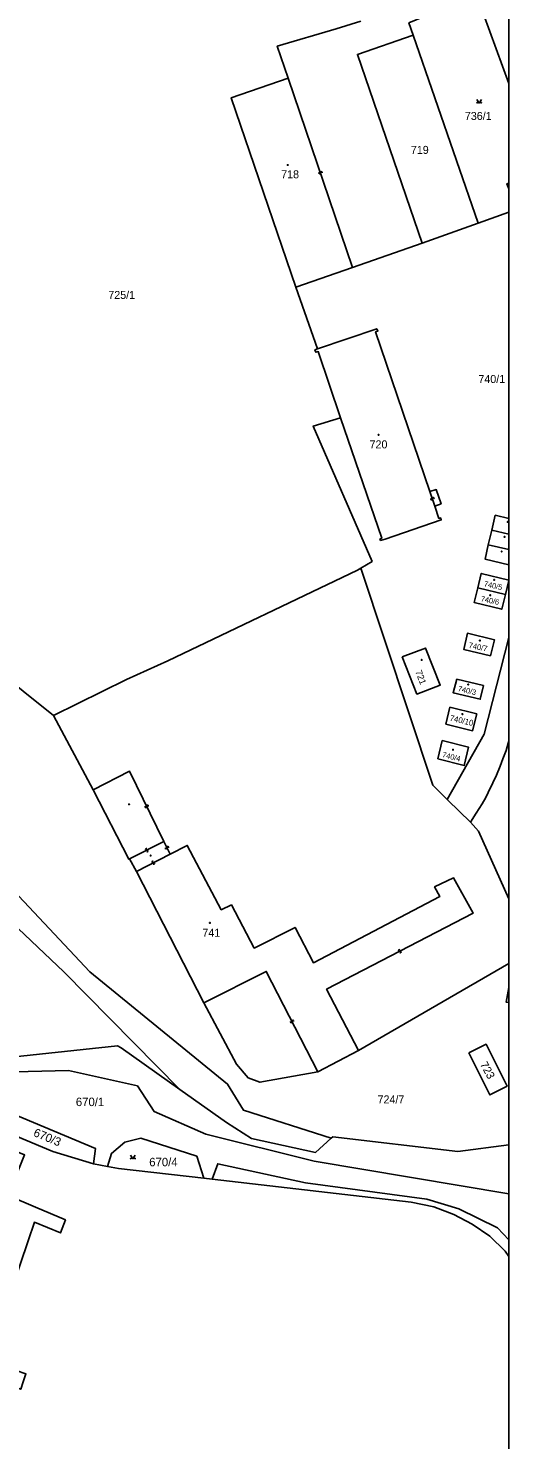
# Model space of a CAD drawing. Extents: x -600391 to -599491, y -1160176 to -1159402.
# Drawn here: x -599592.8 to -599490.8, y -1159973.1 to -1159673.2 of the extents above; entities that cross this region are included whole.
import ezdxf

# ---------------------------------------------------------------- set-up
doc = ezdxf.new("R2010")
doc.units = 0
for name, color, linetype in [('Level 1', 7, 'Continuous'), ('Level 13', 7, 'Continuous'), ('Level 3', 7, 'Continuous'), ('Level 4', 7, 'Continuous'), ('Level 5', 7, 'Continuous'), ('Vrstva 63', 7, 'Continuous')]:
    doc.layers.add(name, color=color, linetype=linetype)

msp = doc.modelspace()

# ---------------------------------------------------------------- linework, layer by layer
at = {"layer": 'Level 1'}
for p, q in [((-599497.62, -1159666.09), (-599490.77, -1159684.95)), ((-599490.77, -1159712.29), (-599497.24, -1159714.63)), ((-599494.38, -1159779.82), (-599490.77, -1159780.67)), ((-599490.77, -1159783.97), (-599495.12, -1159782.97)), ((-599491.49, -1159793.51), (-599490.77, -1159790.54)), ((-599522.69, -1159890.4), (-599490.77, -1159871.89))]:
    msp.add_line(p, q, dxfattribs=at)
for points in [[(-599497.62, -1159666.09), (-599511.98, -1159672.07), (-599511.1, -1159674.67)], [(-599537.6, -1159683.79), (-599539.94, -1159677.03), (-599527.44, -1159673.35), (-599522.15, -1159671.73)], [(-599511.1, -1159674.67), (-599522.91, -1159678.77), (-599509.17, -1159718.89)], [(-599511.1, -1159674.67), (-599497.24, -1159714.63)], [(-599537.6, -1159683.79), (-599549.69, -1159687.96), (-599535.97, -1159728.23)], [(-599490.77, -1159707.33), (-599491.15, -1159706.23), (-599490.77, -1159706.1)], [(-599497.24, -1159714.63), (-599509.17, -1159718.89)], [(-599509.17, -1159718.89), (-599523.93, -1159724.01)], [(-599523.93, -1159724.01), (-599535.97, -1159728.23)], [(-599535.97, -1159728.23), (-599531.41, -1159741.34)], [(-599531.41, -1159741.34), (-599518.8, -1159737.05), (-599518.59, -1159737.57), (-599519.05, -1159737.74), (-599507.52, -1159771.61)], [(-599531.41, -1159741.34), (-599531.92, -1159741.55), (-599531.74, -1159742.03), (-599531.22, -1159741.9), (-599526.51, -1159755.98)], [(-599526.51, -1159755.98), (-599532.3, -1159757.75), (-599519.81, -1159786.48), (-599522.15, -1159787.9)], [(-599506.45, -1159774.72), (-599505.61, -1159777.37), (-599505.23, -1159777.23), (-599505.1, -1159777.68), (-599517.02, -1159781.75), (-599517.99, -1159782.03), (-599518.12, -1159781.73), (-599517.74, -1159781.57), (-599526.51, -1159755.98)], [(-599753.71, -1159763.28), (-599749.4, -1159769.94), (-599727.76, -1159798.93), (-599714.51, -1159816.26), (-599697.25, -1159839.07), (-599689.39, -1159847.67), (-599678.59, -1159857.57), (-599666.21, -1159866.59), (-599654.11, -1159874.19), (-599640.99, -1159880.78), (-599626.25, -1159886.88), (-599606.79, -1159894.4), (-599598.5, -1159895.01), (-599584.26, -1159894.68), (-599569.62, -1159897.92), (-599566.09, -1159903.38), (-599555.13, -1159908.18), (-599532.12, -1159913.92), (-599490.77, -1159920.87)], [(-599507.52, -1159771.61), (-599506.18, -1159771.22), (-599505.14, -1159774.24), (-599506.45, -1159774.72)], [(-599494.38, -1159779.82), (-599493.64, -1159776.69), (-599490.77, -1159777.39)], [(-599495.12, -1159782.97), (-599494.38, -1159779.82)], [(-599495.12, -1159782.97), (-599495.8, -1159786), (-599490.77, -1159787.2)], [(-599522.15, -1159787.9), (-599522.86, -1159788.33), (-599563.15, -1159807.58), (-599571.93, -1159811.59), (-599587.46, -1159819.24)], [(-599503.87, -1159837.09), (-599506.89, -1159834.06), (-599522.15, -1159787.9)], [(-599490.77, -1159790.44), (-599496.6, -1159789.04), (-599497.33, -1159792.11)], [(-599497.33, -1159792.11), (-599498.09, -1159795.25), (-599492.25, -1159796.66), (-599491.49, -1159793.51)], [(-599491.49, -1159793.51), (-599497.33, -1159792.11)], [(-599560.62, -1159898.7), (-599573.09, -1159889.87), (-599573.88, -1159889.45), (-599607.04, -1159892.98), (-599652.03, -1159872.89), (-599667.25, -1159861.02), (-599687.91, -1159844.99), (-599722.17, -1159800.44)], [(-599503.87, -1159837.09), (-599495.98, -1159823.18), (-599490.77, -1159802.63)], [(-599494.62, -1159806.55), (-599493.8, -1159803.13), (-599499.54, -1159801.75), (-599500.34, -1159805.17), (-599494.62, -1159806.55)], [(-599657.03, -1159804.78), (-599613.02, -1159847.44), (-599585.27, -1159873.69), (-599560.62, -1159898.7)], [(-599513.43, -1159806.76), (-599508.42, -1159804.9), (-599505.31, -1159812.75), (-599510.27, -1159814.68), (-599513.43, -1159806.76)], [(-599600.38, -1159808.9), (-599587.46, -1159819.24)], [(-599501.83, -1159811.48), (-599496.14, -1159812.86), (-599496.82, -1159815.76), (-599502.58, -1159814.38), (-599501.83, -1159811.48)], [(-599503.28, -1159817.43), (-599497.58, -1159818.9), (-599498.44, -1159822.46), (-599504.12, -1159821.07), (-599503.28, -1159817.43)], [(-599587.46, -1159819.24), (-599579, -1159835.01)], [(-599504.92, -1159824.53), (-599499.29, -1159825.99), (-599500.23, -1159829.88), (-599505.82, -1159828.43), (-599504.92, -1159824.53)], [(-599490.77, -1159824.68), (-599490.89, -1159825.1), (-599491.35, -1159826.63), (-599492, -1159828.42), (-599492.62, -1159830.02), (-599493.41, -1159831.88), (-599494.15, -1159833.56), (-599495.14, -1159835.61), (-599495.65, -1159836.63), (-599496.44, -1159837.99), (-599497.66, -1159839.95), (-599498.89, -1159841.91)], [(-599528.47, -1159909.07), (-599547.1, -1159903.06), (-599550.47, -1159897.53), (-599579.75, -1159873.69), (-599603.52, -1159848.43), (-599607.94, -1159843.45), (-599616.53, -1159835.36)], [(-599579, -1159835.01), (-599571.47, -1159849.76), (-599571.28, -1159849.7)], [(-599498.89, -1159841.91), (-599503.68, -1159837.21), (-599503.87, -1159837.09)], [(-599498.89, -1159841.91), (-599497.17, -1159843.78), (-599490.77, -1159858.21)], [(-599571.28, -1159849.7), (-599569.83, -1159852.34)], [(-599569.83, -1159852.34), (-599555.51, -1159880.29)], [(-599490.77, -1159880.22), (-599491.31, -1159880.16), (-599490.77, -1159877.02)], [(-599555.51, -1159880.29), (-599548.61, -1159893.33), (-599546.14, -1159896.21), (-599543.62, -1159897.15), (-599531.3, -1159894.91)], [(-599578.95, -1159914.46), (-599578.55, -1159911.22), (-599596.11, -1159903.88), (-599598.49, -1159901.19), (-599626.57, -1159890.89), (-599627.69, -1159893.15)], [(-599531.3, -1159894.91), (-599522.69, -1159890.4)], [(-599499.27, -1159890.9), (-599495.59, -1159889.09), (-599491.11, -1159897.96), (-599494.77, -1159899.84), (-599499.27, -1159890.9)], [(-599528.47, -1159909.07), (-599531.84, -1159912.06), (-599545.39, -1159909.12), (-599550.74, -1159905.69), (-599560.62, -1159898.7)], [(-599599.13, -1159907.08), (-599587.58, -1159911.88), (-599578.95, -1159914.46)], [(-599490.77, -1159910.46), (-599501.58, -1159911.87), (-599528.1, -1159908.74), (-599528.47, -1159909.07)], [(-599624.96, -1159950.28), (-599610.29, -1159954.8), (-599610.87, -1159956.69), (-599596.78, -1159961.57), (-599594.41, -1159962.38), (-599593.86, -1159960.78), (-599593.31, -1159959.08), (-599593.73, -1159958.98), (-599596.14, -1159958.11), (-599601.47, -1159956.19), (-599592.82, -1159930.88), (-599591.51, -1159926.91), (-599585.94, -1159929.16), (-599584.91, -1159926.39), (-599591.27, -1159923.7), (-599597.04, -1159921.2), (-599593.57, -1159912.61), (-599599.02, -1159910.35)], [(-599555.49, -1159917.56), (-599557.01, -1159912.88), (-599568.88, -1159909.04), (-599572.3, -1159909.85), (-599575.12, -1159912.26), (-599575.95, -1159915.03)], [(-599578.95, -1159914.46), (-599575.95, -1159915.03)], [(-599490.77, -1159930.62), (-599493.16, -1159928.08), (-599501.37, -1159924.05), (-599508.17, -1159922.03), (-599533.9, -1159918.51), (-599552.56, -1159914.48), (-599553.78, -1159917.76)], [(-599575.95, -1159915.03), (-599573.62, -1159915.47), (-599555.49, -1159917.56)], [(-599555.49, -1159917.56), (-599553.78, -1159917.76)], [(-599553.78, -1159917.76), (-599511.52, -1159922.64), (-599506.67, -1159923.62), (-599502.42, -1159925.23), (-599498.52, -1159927.32), (-599494.79, -1159929.88), (-599491.53, -1159933.07), (-599490.77, -1159934.15)]]:
    msp.add_lwpolyline(points, dxfattribs=at)
at = {"layer": 'Level 13'}
for centre, start, end in [((-599530.93, -1159703.96), 145.9302, 18.5202), ((-599530.58, -1159703.84), 326.1446, 198.2426), ((-599507.16, -1159773.22), 146.1441, 18.7341), ((-599506.82, -1159773.1), 326.3586, 198.4566), ((-599567.83, -1159838.61), 153.1973, 25.7873), ((-599567.49, -1159838.45), 333.4117, 205.5097), ((-599567.73, -1159847.68), 64.3512, 296.9412), ((-599567.57, -1159848), 244.5657, 116.6637), ((-599563.53, -1159847.4), 153.2989, 25.8889), ((-599563.19, -1159847.24), 333.5134, 205.6114), ((-599566.34, -1159850.35), 64.2982, 296.8882), ((-599566.18, -1159850.67), 244.5126, 116.6106), ((-599513.99, -1159869.16), 64.5572, 297.1472), ((-599513.83, -1159869.48), 244.7717, 116.8697), ((-599536.95, -1159884.33), 154.6216, 26.7196), ((-599536.63, -1159884.17), 334.4072, 206.9972)]:
    msp.add_arc(centre, 0.184, start, end, dxfattribs=at)
at = {"layer": 'Level 3'}
for points in [[(-599537.6, -1159683.79), (-599523.93, -1159724.01)], [(-599507.52, -1159771.61), (-599506.45, -1159774.72)], [(-599579, -1159835.01), (-599571.29, -1159831.09), (-599564.02, -1159845.97)], [(-599564.02, -1159845.97), (-599571.28, -1159849.7)], [(-599562.69, -1159848.68), (-599569.83, -1159852.34)], [(-599564.02, -1159845.97), (-599562.69, -1159848.68)], [(-599562.69, -1159848.68), (-599559.05, -1159846.83), (-599551.82, -1159860.51), (-599549.67, -1159859.48), (-599544.82, -1159868.65), (-599536.14, -1159864.24), (-599532.27, -1159871.75), (-599505.39, -1159857.67), (-599506.53, -1159855.66), (-599502.53, -1159853.71), (-599498.36, -1159861.26), (-599529.46, -1159877.38), (-599522.69, -1159890.4)], [(-599531.3, -1159894.91), (-599542.28, -1159873.59), (-599555.51, -1159880.29)]]:
    msp.add_lwpolyline(points, dxfattribs=at)
at = {"layer": 'Level 5'}
for points in [[(-599497.56, -1159688.34), (-599497.06, -1159689.09), (-599496.56, -1159688.34)], [(-599571.09, -1159912.67), (-599570.59, -1159913.42), (-599570.09, -1159912.67)]]:
    msp.add_lwpolyline(points, dxfattribs=at)
for centre, radius in [((-599497.51, -1159689.04), 0.05), ((-599496.61, -1159689.04), 0.05), ((-599537.7, -1159702.26), 0.09), ((-599537.7, -1159702.26), 0.0521), ((-599518.42, -1159759.6), 0.09), ((-599518.42, -1159759.6), 0.0521), ((-599491, -1159778.1), 0.09), ((-599491, -1159778.1), 0.0521), ((-599491.66, -1159781.29), 0.09), ((-599491.66, -1159781.29), 0.0521), ((-599492.28, -1159784.38), 0.09), ((-599492.28, -1159784.38), 0.0521), ((-599493.87, -1159790.43), 0.09), ((-599493.87, -1159790.43), 0.0521), ((-599494.71, -1159793.68), 0.09), ((-599494.71, -1159793.68), 0.0521), ((-599496.9, -1159803.32), 0.09), ((-599496.9, -1159803.32), 0.0521), ((-599509.26, -1159807.42), 0.09), ((-599509.26, -1159807.42), 0.0521), ((-599499.37, -1159812.64), 0.09), ((-599499.37, -1159812.64), 0.0521), ((-599500.61, -1159818.93), 0.09), ((-599500.61, -1159818.93), 0.0521), ((-599502.61, -1159826.5), 0.09), ((-599502.61, -1159826.5), 0.0521), ((-599571.39, -1159838.1), 0.09), ((-599571.39, -1159838.1), 0.0521), ((-599566.82, -1159848.99), 0.09), ((-599566.82, -1159848.99), 0.0521), ((-599554.23, -1159863.31), 0.09), ((-599554.23, -1159863.31), 0.0521), ((-599571.04, -1159913.37), 0.05), ((-599570.14, -1159913.37), 0.05)]:
    msp.add_circle(centre, radius, dxfattribs=at)
at = {"layer": 'Vrstva 63'}
msp.add_lwpolyline([(-600391.01, -1159401.77), (-599490.77, -1159401.77), (-599490.77, -1160176.08), (-600391.01, -1160176.08)], close=True, dxfattribs=at)

# ---------------------------------------------------------------- texts
at = {"layer": 'Level 4'}
for s, height, p in [('736/1', 1.7, (-599500.09, -1159692.69)), ('719', 1.7, (-599511.56, -1159699.9)), ('718', 1.7, (-599539.1, -1159705.08)), ('725/1', 1.7, (-599575.81, -1159730.72)), ('740/1', 1.7, (-599497.22, -1159748.58)), ('720', 1.7, (-599520.33, -1159762.47)), ('741', 1.7, (-599555.83, -1159866.24)), ('724/7', 1.7, (-599518.63, -1159901.65)), ('670/1', 1.8, (-599582.7, -1159902.22)), ('670/4', 1.8, (-599567.12, -1159915.01))]:
    msp.add_text(s, height=height, dxfattribs=at).set_placement(p)
for s, height, rotation, p in [('740/5', 1.14, 347.4, (-599496.13, -1159791.75)), ('740/6', 1.14, 348.3, (-599496.79, -1159794.94)), ('740/7', 1.2, 348.3, (-599499.37, -1159804.84)), ('721', 1.4, 290.7, (-599510.64, -1159809.89)), ('740/3', 1.14, 346.5, (-599501.67, -1159814.01)), ('740/10', 1.24, 346.6882, (-599503.39, -1159820.3)), ('740/4', 1.14, 345.6, (-599505, -1159828.04)), ('723', 1.7, 298.8, (-599496.93, -1159893.34)), ('670/3', 1.8, 337.3153, (-599591.87, -1159908.51))]:
    msp.add_text(s, height=height, rotation=rotation, dxfattribs=at).set_placement(p)

doc.saveas('drawing.dxf')
